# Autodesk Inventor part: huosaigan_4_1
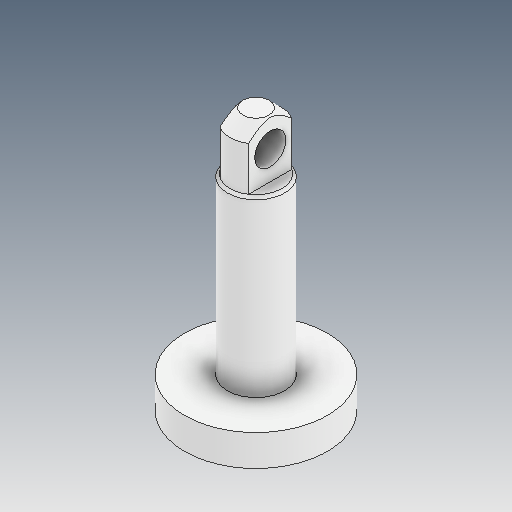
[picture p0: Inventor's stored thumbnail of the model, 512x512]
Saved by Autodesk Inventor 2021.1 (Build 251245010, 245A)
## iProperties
Created: 2021-05
Part Number: huosaigan_4_1
Material: Ogólny
Document SubType Name: Modeling
Designer: user
Density: 1 g/cm^3
Appearance: Domyślna
Author: user
Revision Number: ÈÎºÎ
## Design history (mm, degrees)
feature "ÊäÈë1"
node "Bryła1"
